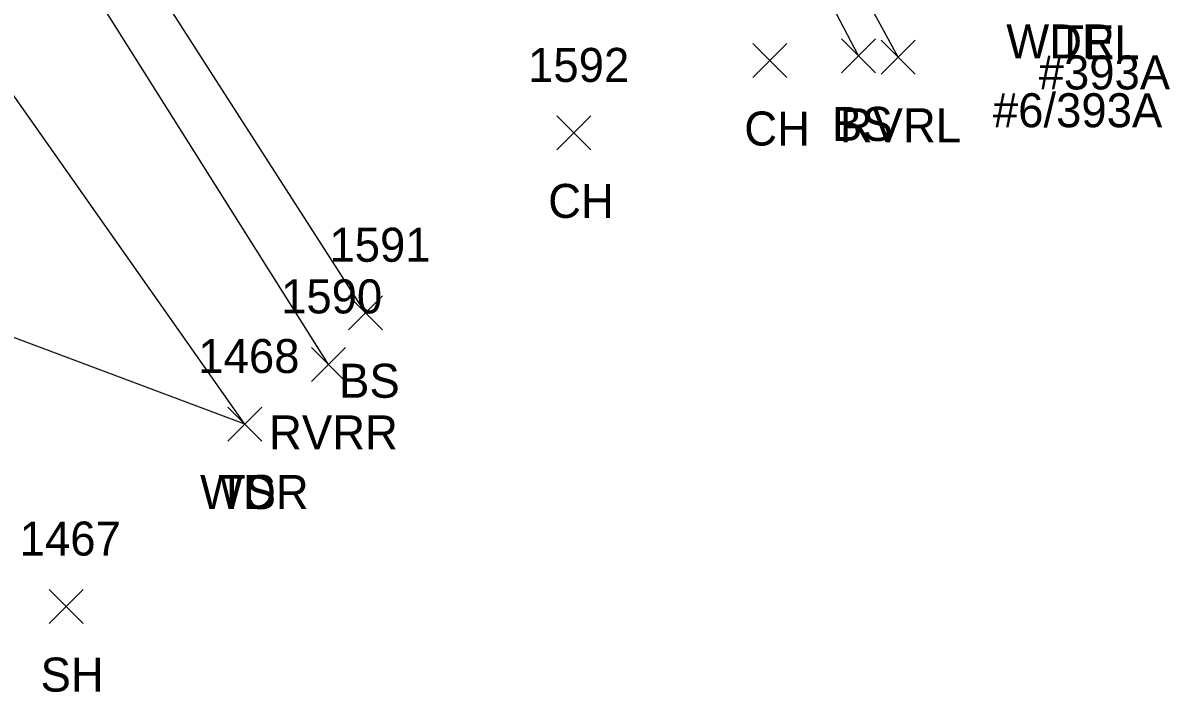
# Model space of a CAD drawing. Extents: x 1653908 to 1654393, y 539913 to 544256.
# Drawn here: x 1654147.8 to 1654215.3, y 541434 to 541473.4 of the extents above; entities that cross this region are included whole.
import ezdxf

# ---------------------------------------------------------------- set-up
doc = ezdxf.new("R2010")
doc.units = 0
for name, color, linetype in [('L_A', 7, 'Continuous'), ('L_I', 7, 'Continuous'), ('L_TIC', 7, 'Continuous'), ('LAWA', 7, 'Continuous'), ('LAWE', 7, 'Continuous'), ('LELB', 7, 'Continuous'), ('U_A', 7, 'Continuous'), ('U_C', 7, 'Continuous')]:
    doc.layers.add(name, color=color, linetype=linetype)

msp = doc.modelspace()

# ---------------------------------------------------------------- linework, layer by layer
at = {"layer": 'L_TIC'}
for points in [[(1654190.724, 541470.172), (1654192.724, 541472.172)], [(1654192.724, 541470.172), (1654190.724, 541472.172)], [(1654195.933, 541470.448), (1654197.933, 541472.448)], [(1654197.933, 541470.448), (1654195.933, 541472.448)], [(1654198.262, 541470.362), (1654200.262, 541472.362)], [(1654200.262, 541470.362), (1654198.262, 541472.362)], [(1654179.188, 541465.914), (1654181.188, 541467.914)], [(1654181.188, 541465.914), (1654179.188, 541467.914)], [(1654166.935, 541455.336), (1654168.935, 541457.336)], [(1654168.935, 541455.336), (1654166.935, 541457.336)], [(1654164.746, 541452.299), (1654166.746, 541454.299)], [(1654166.746, 541452.299), (1654164.746, 541454.299)], [(1654159.837, 541448.792), (1654161.837, 541450.792)], [(1654161.837, 541448.792), (1654159.837, 541450.792)], [(1654159.837, 541448.792), (1654161.837, 541450.792)], [(1654161.837, 541448.792), (1654159.837, 541450.792)], [(1654149.328, 541438.054), (1654151.328, 541440.054)], [(1654151.328, 541438.054), (1654149.328, 541440.054)]]:
    msp.add_lwpolyline(points, dxfattribs=at)
at = {"layer": 'LAWA'}
msp.add_lwpolyline([(1654160.837, 541449.792), (1654138.355, 541481.731), (1654119.295, 541498.076), (1654123.998, 541512.093), (1654120.708, 541524.249), (1654111.103, 541539.428)], dxfattribs=at)
at = {"layer": 'LAWE'}
for points in [[(1654199.262, 541471.362), (1654181.864, 541503.275), (1654178.823, 541509.623), (1654164.463, 541535.09), (1654153.73, 541550.437), (1654126.864, 541584.5), (1654110.114, 541605.799), (1654090.445, 541629.393), (1654082.441, 541647.339), (1654069.568, 541661.666), (1654051.083, 541684.152), (1654038.474, 541696.154), (1654026.73, 541704.451), (1654010.803, 541724.448), (1653979.677, 541745.496), (1653961.842, 541751.354), (1653943.478, 541769.149)], [(1654165.746, 541453.299), (1654145.371, 541485.64), (1654128.334, 541517.883), (1654118.977, 541538.058), (1654102.878, 541558.426), (1654087.635, 541571.291), (1654080.686, 541574.229), (1654068.7, 541590.649), (1654047.982, 541616.505), (1654043.581, 541623.07), (1654031.273, 541642.945), (1654001.648, 541675.052), (1653981.817, 541702.274), (1653972.906, 541712.113), (1653946.212, 541722.655), (1653929.327, 541730.47)]]:
    msp.add_lwpolyline(points, dxfattribs=at)
at = {"layer": 'LELB'}
for points in [[(1654196.933, 541471.448), (1654180.81, 541502.224), (1654177.717, 541510.013), (1654161.804, 541533.8), (1654150.942, 541550.189), (1654125.245, 541583.387), (1654108.345, 541603.179), (1654088.224, 541626.265), (1654081.332, 541637.747)], [(1654167.935, 541456.336), (1654149.347, 541485.287), (1654131.616, 541518.698), (1654120.79, 541539.282), (1654104.431, 541560.103), (1654087.958, 541576.781)], [(1654160.837, 541449.792), (1654142.766, 541456.54), (1654127.364, 541469.26), (1654113.217, 541497.926)]]:
    msp.add_lwpolyline(points, dxfattribs=at)

# ---------------------------------------------------------------- texts
at = {"layer": 'L_A'}
for s, p in [('WDR', (1654205.624, 541471.294)), ('CH', (1654190.212, 541466.172)), ('BS', (1654195.374, 541466.448)), ('RVRL', (1654195.829, 541466.362)), ('CH', (1654178.676, 541461.914)), ('BS', (1654166.376, 541451.336)), ('RVRR', (1654162.258, 541448.299)), ('WDR', (1654158.199, 541444.792)), ('TS', (1654159.246, 541444.792)), ('SH', (1654148.816, 541434.054))]:
    msp.add_text(s, height=2, dxfattribs=at).set_placement(p)
at = {"layer": 'L_I'}
for s, p in [('1592', (1654177.495, 541469.914)), ('1591', (1654165.809, 541459.336)), ('1590', (1654162.967, 541456.299)), ('1468', (1654158.097, 541452.792)), ('1468', (1654158.097, 541452.792)), ('1467', (1654147.588, 541442.054))]:
    msp.add_text(s, height=2, dxfattribs=at).set_placement(p)
at = {"layer": 'U_A'}
msp.add_text('TEL', height=2, dxfattribs=at).set_placement((1654208.559, 541471.248))
at = {"layer": 'U_C'}
for s, p in [('#393A', (1654207.529, 541469.472)), ('#6/393A', (1654204.835, 541467.248))]:
    msp.add_text(s, height=2, dxfattribs=at).set_placement(p)

doc.saveas('drawing.dxf')
